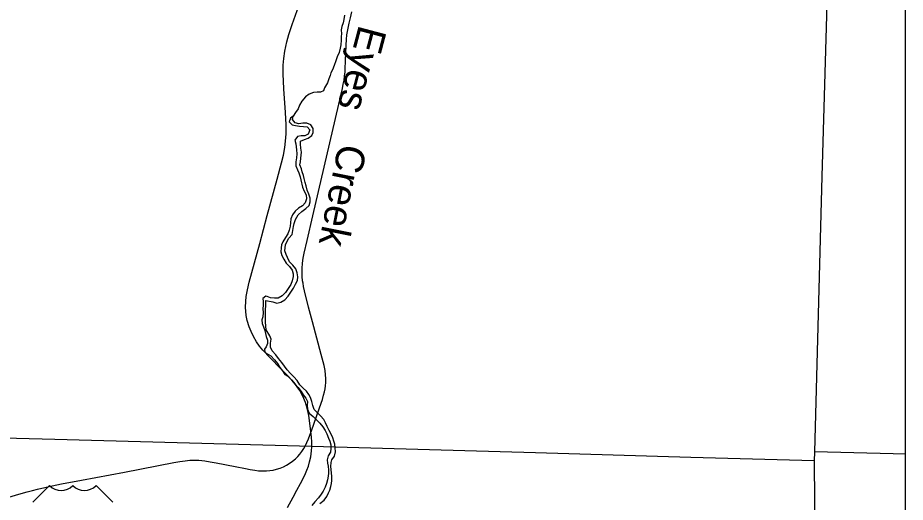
# Model space of a CAD drawing. Extents: x -6.3 to 34, y 0 to 22.
# Drawn here: x 10.181 to 12.189, y 13.296 to 14.392 of the extents above; entities that cross this region are included whole.
import ezdxf

# ---------------------------------------------------------------- set-up
doc = ezdxf.new("R2010")
doc.units = 0
for name, color, linetype in [('GM_X_Minor_River', 7, 'Continuous'), ('GM_X_Minor_River_Text', 7, 'Continuous'), ('GM_X_Rail_Line', 7, 'Continuous'), ('GM_X_State_Route', 7, 'Continuous'), ('GM_X_Township', 7, 'Continuous'), ('GM_X_US_Shield', 7, 'Continuous'), ('SH_Text', 7, 'Continuous')]:
    doc.layers.add(name, color=color, linetype=linetype)

msp = doc.modelspace()

# ---------------------------------------------------------------- linework, layer by layer
at = {"layer": 'GM_X_Minor_River'}
msp.add_line((10.7398, 13.6365), (10.7432, 13.6333), dxfattribs=at)
for points in [[(10.9205, 14.3979), (10.9188, 14.3888), (10.9174, 14.3812), (10.9146, 14.3729), (10.9131, 14.3648), (10.9132, 14.3562), (10.9131, 14.3497), (10.9129, 14.3419), (10.9117, 14.331), (10.9102, 14.3237), (10.908, 14.314), (10.904, 14.3041), (10.9007, 14.2952), (10.8972, 14.2843), (10.8934, 14.2749), (10.8896, 14.268), (10.8876, 14.2615), (10.8846, 14.2545), (10.8816, 14.2448), (10.8752, 14.2336), (10.873, 14.2268), (10.8663, 14.2241), (10.8585, 14.2237), (10.8499, 14.2234), (10.8404, 14.2199), (10.8319, 14.2138), (10.824, 14.2036), (10.8184, 14.1944), (10.8154, 14.1863), (10.8098, 14.1779), (10.8039, 14.1701)], [(10.8039, 14.1701), (10.7982, 14.1653), (10.7955, 14.1572), (10.802, 14.15), (10.8098, 14.1483), (10.8184, 14.1471), (10.8277, 14.1464), (10.8358, 14.1455), (10.8416, 14.1385), (10.8383, 14.1291), (10.8308, 14.1254), (10.8225, 14.1253), (10.814, 14.1241), (10.8076, 14.1152), (10.81, 14.1069), (10.8111, 14.1002), (10.812, 14.0934), (10.8126, 14.0846), (10.8117, 14.0752), (10.81, 14.0661), (10.8101, 14.0573), (10.8138, 14.0482), (10.8167, 14.0415), (10.8197, 14.0324), (10.8216, 14.0257), (10.8251, 14.0088), (10.8291, 14), (10.8334, 13.9917), (10.8345, 13.9829), (10.8312, 13.9737), (10.8251, 13.9667), (10.8166, 13.9619), (10.8086, 13.955), (10.8025, 13.9464), (10.7992, 13.9375), (10.7983, 13.9286), (10.7974, 13.9206), (10.7954, 13.9117), (10.7921, 13.9033), (10.787, 13.895), (10.7809, 13.8858), (10.7781, 13.8787), (10.7772, 13.872), (10.7765, 13.8629), (10.7784, 13.8543), (10.7829, 13.8463), (10.7882, 13.837), (10.7961, 13.83), (10.8021, 13.8215), (10.8045, 13.8132), (10.8041, 13.8067), (10.8019, 13.7976), (10.7986, 13.7887), (10.7869, 13.7706), (10.7792, 13.7635), (10.7704, 13.7582), (10.7621, 13.7579), (10.7531, 13.7591), (10.745, 13.7621), (10.7422, 13.7628)], [(10.7423, 13.7529), (10.7583, 13.7495), (10.7675, 13.7468), (10.776, 13.7492), (10.785, 13.754), (10.7927, 13.7629), (10.8049, 13.7807), (10.8095, 13.7894), (10.814, 13.7983), (10.8147, 13.8061), (10.8136, 13.8152), (10.8101, 13.8242), (10.8033, 13.8327), (10.7962, 13.8405), (10.7912, 13.8498), (10.7882, 13.8565), (10.7855, 13.865), (10.7862, 13.8718), (10.7872, 13.8788), (10.7897, 13.8856), (10.7943, 13.894), (10.8017, 13.9024), (10.8034, 13.9113), (10.8051, 13.9199), (10.8061, 13.9269), (10.8096, 13.9361), (10.8152, 13.9463), (10.8237, 13.9539), (10.8329, 13.9608), (10.8406, 13.9676), (10.8429, 13.976), (10.8428, 13.9845), (10.8396, 13.9936), (10.8356, 14.0024), (10.8337, 14.0123), (10.8315, 14.02), (10.8291, 14.0286), (10.8279, 14.0356), (10.8245, 14.0436), (10.8229, 14.0504), (10.8196, 14.06), (10.8206, 14.0665), (10.8215, 14.0751), (10.8225, 14.0816), (10.8229, 14.0886), (10.8218, 14.0974), (10.8207, 14.1065), (10.8211, 14.1133), (10.8301, 14.1173), (10.8381, 14.12), (10.8464, 14.1258), (10.8491, 14.1329), (10.8493, 14.142), (10.8443, 14.1502), (10.8354, 14.1538), (10.8264, 14.1537), (10.8173, 14.1528), (10.8085, 14.155), (10.8029, 14.1625), (10.8039, 14.1701)], [(10.7422, 13.7628), (10.7354, 13.7573), (10.7362, 13.7503), (10.7363, 13.742), (10.7355, 13.7337), (10.7361, 13.7253), (10.7353, 13.716), (10.7335, 13.7092), (10.7338, 13.7009), (10.7369, 13.6931), (10.74, 13.6851), (10.7429, 13.6711)], [(10.7428, 13.6867), (10.7415, 13.7038), (10.7417, 13.72), (10.7423, 13.7529)], [(10.8645, 13.2936), (10.874, 13.3012), (10.8803, 13.3091), (10.8839, 13.3175), (10.8874, 13.324), (10.8894, 13.3321), (10.8906, 13.3391), (10.8913, 13.3456), (10.8917, 13.3552), (10.8911, 13.362), (10.8903, 13.3703), (10.8897, 13.3773), (10.8901, 13.3862), (10.8918, 13.3927), (10.8974, 13.4008), (10.8997, 13.4102), (10.8993, 13.4193), (10.8982, 13.4279), (10.896, 13.4349), (10.8941, 13.4419), (10.8904, 13.4504), (10.8859, 13.4589), (10.8814, 13.4677), (10.8774, 13.4763), (10.8734, 13.4837), (10.8663, 13.492), (10.8584, 13.4994), (10.8516, 13.5061), (10.8484, 13.5149), (10.8465, 13.5245), (10.8433, 13.5331), (10.8393, 13.54), (10.8345, 13.5473), (10.8267, 13.5547), (10.8191, 13.5622), (10.813, 13.5715), (10.8059, 13.58), (10.7981, 13.5877), (10.7904, 13.5962), (10.7846, 13.6042), (10.7788, 13.6127), (10.7712, 13.6217), (10.7646, 13.63), (10.7565, 13.639), (10.753, 13.647), (10.7529, 13.6561), (10.7541, 13.665), (10.7514, 13.6732), (10.7428, 13.6867)], [(10.7429, 13.6711), (10.7459, 13.663), (10.7459, 13.6555), (10.7431, 13.6482)], [(10.7431, 13.6482), (10.7395, 13.6427), (10.7398, 13.6365)], [(10.7432, 13.6333), (10.7538, 13.6275), (10.7619, 13.6188), (10.7685, 13.6102), (10.7743, 13.6015), (10.7798, 13.5935), (10.7856, 13.5857), (10.7924, 13.5814), (10.8006, 13.5732), (10.8087, 13.5636), (10.8155, 13.5559), (10.8226, 13.5466), (10.8269, 13.5396), (10.8329, 13.5319), (10.8366, 13.5242), (10.836, 13.5153), (10.8366, 13.507), (10.8403, 13.4977), (10.8492, 13.49), (10.8563, 13.4833), (10.8644, 13.4753), (10.8715, 13.4673), (10.8763, 13.4586), (10.88, 13.4508), (10.8843, 13.4415), (10.8872, 13.4348), (10.8896, 13.4259), (10.8897, 13.4179), (10.8883, 13.4098), (10.8837, 13.4014), (10.8812, 13.392), (10.8818, 13.3848), (10.8832, 13.3778), (10.8841, 13.3692), (10.8844, 13.3622), (10.8837, 13.3552), (10.8822, 13.3468), (10.8797, 13.3385), (10.8767, 13.3304), (10.8719, 13.3212), (10.8678, 13.3144), (10.8612, 13.3063), (10.8535, 13.2976), (10.8464, 13.2887)]]:
    msp.add_lwpolyline(points, dxfattribs=at)
at = {"layer": 'GM_X_Rail_Line'}
msp.add_lwpolyline([(10.1434, 13.3027), (10.1834, 13.3146), (10.2026, 13.3202), (10.2146, 13.3233), (10.2254, 13.326), (10.2586, 13.3335), (10.2801, 13.3378), (10.3252, 13.3464), (10.4223, 13.3648), (10.5345, 13.3863), (10.5477, 13.3887), (10.5596, 13.3903), (10.5703, 13.3913), (10.5808, 13.3916), (10.591, 13.3913), (10.6045, 13.3899), (10.6163, 13.3881), (10.6298, 13.3857), (10.6728, 13.3771), (10.6964, 13.3725), (10.7066, 13.3706), (10.7171, 13.3687), (10.7259, 13.3677), (10.735, 13.3671), (10.7438, 13.3672), (10.7515, 13.3679), (10.7592, 13.3692), (10.7668, 13.3709), (10.7751, 13.3737), (10.7822, 13.3767), (10.7893, 13.3804), (10.7954, 13.3837), (10.8028, 13.3891), (10.8091, 13.3944), (10.815, 13.4), (10.8195, 13.4052), (10.8241, 13.4111), (10.8286, 13.4182), (10.8321, 13.4244), (10.8353, 13.4316), (10.8387, 13.4397), (10.8462, 13.4599), (10.856, 13.4882), (10.8634, 13.5096), (10.8702, 13.529), (10.8731, 13.5384), (10.8751, 13.5458), (10.8766, 13.5527), (10.8777, 13.5598), (10.8782, 13.5675), (10.8783, 13.5761), (10.8777, 13.5849), (10.8763, 13.5946), (10.874, 13.6059), (10.8676, 13.6305), (10.8478, 13.7048), (10.8392, 13.7377), (10.8297, 13.7744), (10.8276, 13.7842), (10.8265, 13.7918), (10.8256, 13.7976), (10.8249, 13.8069), (10.8246, 13.816), (10.8247, 13.8253), (10.8255, 13.8372), (10.8271, 13.8485), (10.8294, 13.8595), (10.8361, 13.8887), (10.8488, 13.944), (10.9125, 14.2194), (10.9155, 14.2326), (10.9176, 14.2425), (10.9193, 14.2511), (10.9206, 14.2605), (10.9215, 14.2702), (10.922, 14.2796), (10.9225, 14.2917), (10.9235, 14.3168), (10.9246, 14.3435), (10.9257, 14.3541), (10.9276, 14.365), (10.9307, 14.3798), (10.9338, 14.3923), (10.9372, 14.406)], dxfattribs=at)
at = {"layer": 'GM_X_State_Route'}
msp.add_lwpolyline([(10.7915, 13.2842), (10.8041, 13.3082), (10.8124, 13.3234), (10.8204, 13.3387), (10.8303, 13.358), (10.8354, 13.3693), (10.8386, 13.3783), (10.8415, 13.3877), (10.8441, 13.3991), (10.846, 13.4124), (10.8463, 13.4218), (10.8462, 13.4332), (10.8457, 13.4439), (10.8435, 13.4632), (10.8396, 13.4927), (10.836, 13.509), (10.8321, 13.5218), (10.8259, 13.5367), (10.8189, 13.5489), (10.815, 13.555), (10.8094, 13.5626), (10.8014, 13.5725), (10.7931, 13.5816), (10.7766, 13.5985), (10.7523, 13.6229), (10.7356, 13.6407), (10.728, 13.6498), (10.7212, 13.6595), (10.7144, 13.6711), (10.7088, 13.6825), (10.7047, 13.6932), (10.7004, 13.7079), (10.6981, 13.7191), (10.6965, 13.7375), (10.697, 13.7504), (10.6979, 13.7619), (10.7005, 13.7768), (10.7044, 13.7939), (10.7284, 13.8816), (10.7455, 13.945), (10.7679, 14.0269), (10.7778, 14.064), (10.7821, 14.0817), (10.7851, 14.0989), (10.7869, 14.1133), (10.7881, 14.13), (10.7884, 14.1504), (10.7868, 14.1777), (10.7833, 14.2318), (10.7817, 14.2658), (10.7818, 14.2849), (10.7833, 14.3003), (10.7855, 14.3167), (10.7896, 14.3377), (10.7942, 14.3544), (10.8017, 14.3769), (10.8171, 14.4191)], dxfattribs=at)
at = {"layer": 'GM_X_Township'}
for points in [[(12.0169, 14.6054), (12.0003, 14.0335), (11.9837, 13.4105), (11.9832, 13.39), (11.7039, 13.3979), (11.3521, 13.4079), (10.8462, 13.4222), (10.2653, 13.4386), (9.9455, 13.4469), (9.2205, 13.4619), (8.9199, 13.4693), (8.5693, 13.4755), (8.5763, 13.7858), (8.5851, 14.1737), (8.5926, 14.4543)], [(12.189, 13.4049), (12.1616, 13.4057), (11.9837, 13.4105), (11.9832, 13.39), (11.9842, 13.205), (11.9845, 13.1562), (11.9852, 13.0258), (11.9853, 13.0174), (11.9723, 12.3546), (11.9703, 12.2549), (11.968, 12.1557), (11.9645, 11.9991), (11.9572, 11.6777), (11.9421, 11.0563), (11.9336, 10.5039), (11.9284, 10.2095), (11.9156, 9.9669)]]:
    msp.add_lwpolyline(points, dxfattribs=at)
at = {"layer": 'GM_X_US_Shield'}
for p, q in [((10.2529, 13.334), (10.2153, 13.2964)), ((10.396, 13.2964), (10.3583, 13.334))]:
    msp.add_line(p, q, dxfattribs=at)
for centre in [(10.2793, 13.3609), (10.332, 13.3609)]:
    msp.add_arc(centre, 0.0376, 225.573, 314.427, dxfattribs=at)
at = {"layer": 'SH_Text'}
msp.add_lwpolyline([(1.8145, 20.7482), (12.189, 20.7482), (12.189, 9.3884), (1.8145, 9.3884)], close=True, dxfattribs=at)

# ---------------------------------------------------------------- texts
at = {"layer": 'GM_X_Minor_River_Text'}
for s, height, rotation, p in [('Eyes', 0.06493, 255.1728, (10.9535, 14.3784)), ('Creek', 0.0649, 258.7061, (10.9074, 14.1097))]:
    msp.add_text(s, height=height, rotation=rotation, dxfattribs=at).set_placement(p)

doc.saveas('drawing.dxf')
